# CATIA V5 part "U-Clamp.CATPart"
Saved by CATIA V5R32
Part number: U-Clamp
Bounding box of the stored display mesh (mm): x -22.987 to 22.987, y -6.35 to 6.35, z -25.4 to 28.702
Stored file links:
  D:\PROJECTS\Project 2022\CATIA V5 6R 2022\Resources\Input file\c14_catia_v5_6r2022_inp\c14_catia_v5_6r2022_inp\U-Clamp.CATPart
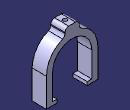
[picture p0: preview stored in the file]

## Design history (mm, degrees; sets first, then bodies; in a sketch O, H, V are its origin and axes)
Body1 (main body)
  Sketch1 on zx-plane, origin (0, 0, 0), H (-1, 0, 0), V (0, 0, 1)
    arc A1 centre (0, 0) radius 17.526 from (17.526, 0) to (-17.526, 0) ccw
    point P1 (-17.526, 0)
    point P2 (17.526, 0)
    line L1 (-17.526, 0) -> (-17.526, -22.352)
    point P3 (-17.526, -22.352)
    line L2 (-17.526, -22.352) -> (-13.462, -22.352)
    point P4 (-13.462, -22.352)
    line L3 (-13.462, -22.352) -> (-13.462, -25.4)
    point P5 (-13.462, -25.4)
    line L4 (-13.462, -25.4) -> (-22.987, -25.4)
    point P6 (-22.987, -25.4)
    line L5 (-22.987, -25.4) -> (-22.987, 0)
    point P7 (-22.987, 0)
    arc A2 centre (0, 0) radius 22.987 from (-22.987, 0) to (-6.35, 22.0925) cw
    point P9 (22.987, 0)
    point P10 (22.987, 0)
    point P11 (22.987, -25.4)
    line L6 (22.987, -25.4) -> (22.987, 0)
    point P12 (13.462, -25.4)
    line L7 (13.462, -25.4) -> (22.987, -25.4)
    point P13 (13.462, -22.352)
    line L8 (13.462, -22.352) -> (13.462, -25.4)
    point P14 (17.526, -22.352)
    line L9 (17.526, -22.352) -> (13.462, -22.352)
    point P15 (17.526, 0)
    line L10 (17.526, 0) -> (17.526, -22.352)
    line L11 (-6.35, 22.0925) -> (-6.35, 28.702)
    point P16 (-6.35, 28.702)
    line L12 (-6.35, 28.702) -> (6.35, 28.702)
    point P17 (6.35, 28.702)
    line L13 (6.35, 28.702) -> (6.35, 22.0925)
    point P18 (6.35, 22.0925)
    arc A3 centre (0, 0) radius 22.987 from (6.35, 22.0925) to (22.987, 0) cw
    radius A1 = 17.526
    distance L3 V = 13.462
    distance H L2 = 22.352
    distance H L4 = 25.4
    distance V L5 = 22.987
    distance P16 P17 = 12.7
    distance L11 V = 6.35
    distance L12 H = 28.702
    coincidence: P1 H, P2 H, P7 H, A2 P18, A2 A3, P2 P15, P9 P10
    tangency: L1 A1, A2 L5
    horizontal: L2 H, L4 H, L12 H
    vertical: L3 V, L5 V, L11 V, L13 V
    concentricity: A2 A1
    symmetry: P7 P10 V, P6 P11 V, L5 L6 V, P5 P12 V, L4 L7 V, P4 P13 V, L3 L8 V, P3 P14 V, L2 L9 V, P1 P15 V, L1 L10 V
  Pad1: profile Sketch1, direction (0, -1, 0), length 6.35, mirrored extent
  Fillet1: radius 3.302, on 4 edges
  Sketch2 on face of Pad1, origin (-0.057, 2.6412, 28.702), H (1, 0, 0), V (0, 1, 0)
    point P1 (0.057, -2.6412)
    reference intersected line E1 through (0.057, 0) direction (0, 1) from yz-plane
    reference intersected line E2 through (0, -2.6412) direction (-1, 0) from zx-plane
    coincidence: E1 P1, E2 P1
  Hole1: placed by Sketch2, at (0, 0, 28.702) direction (0, 0, -1), diameter 3.81, depth 25.4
